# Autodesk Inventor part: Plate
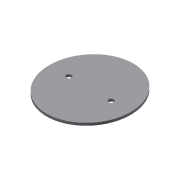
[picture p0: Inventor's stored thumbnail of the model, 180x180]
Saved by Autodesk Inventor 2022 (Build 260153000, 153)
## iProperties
Created: 2009-04
Part Number: Plate
Document SubType Name: Modeling
Designer: Sham
Density: 1 g/cm^3
Material: Generic
Appearance: Default
Author: Sham
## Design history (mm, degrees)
sketch "Sketch1"
  geometry: C1 r 6.25 at (-50, 0); C2 r 6.25 at (50, 0); 4 further points
  constraints: 2 centre point, 1 coincident, 5 other
  dimensions: "d1" = 12.5 diameter of C1; "d2" = 12.5 diameter of C2; "d3" = 100 distance of C2.centre C1.centre; "d4" = 102.5 distance of point (0, 0) point (0, 102.5); "d5" = 96 distance of point (0, 0) point (-96, 0); "d6" = 50 distance of point (0, 0) C1.centre
extrude "Extrusion1" new body sketch "Sketch1" distance "d7" = 6; taper "d8" = 0 deg
body "Solid1"
